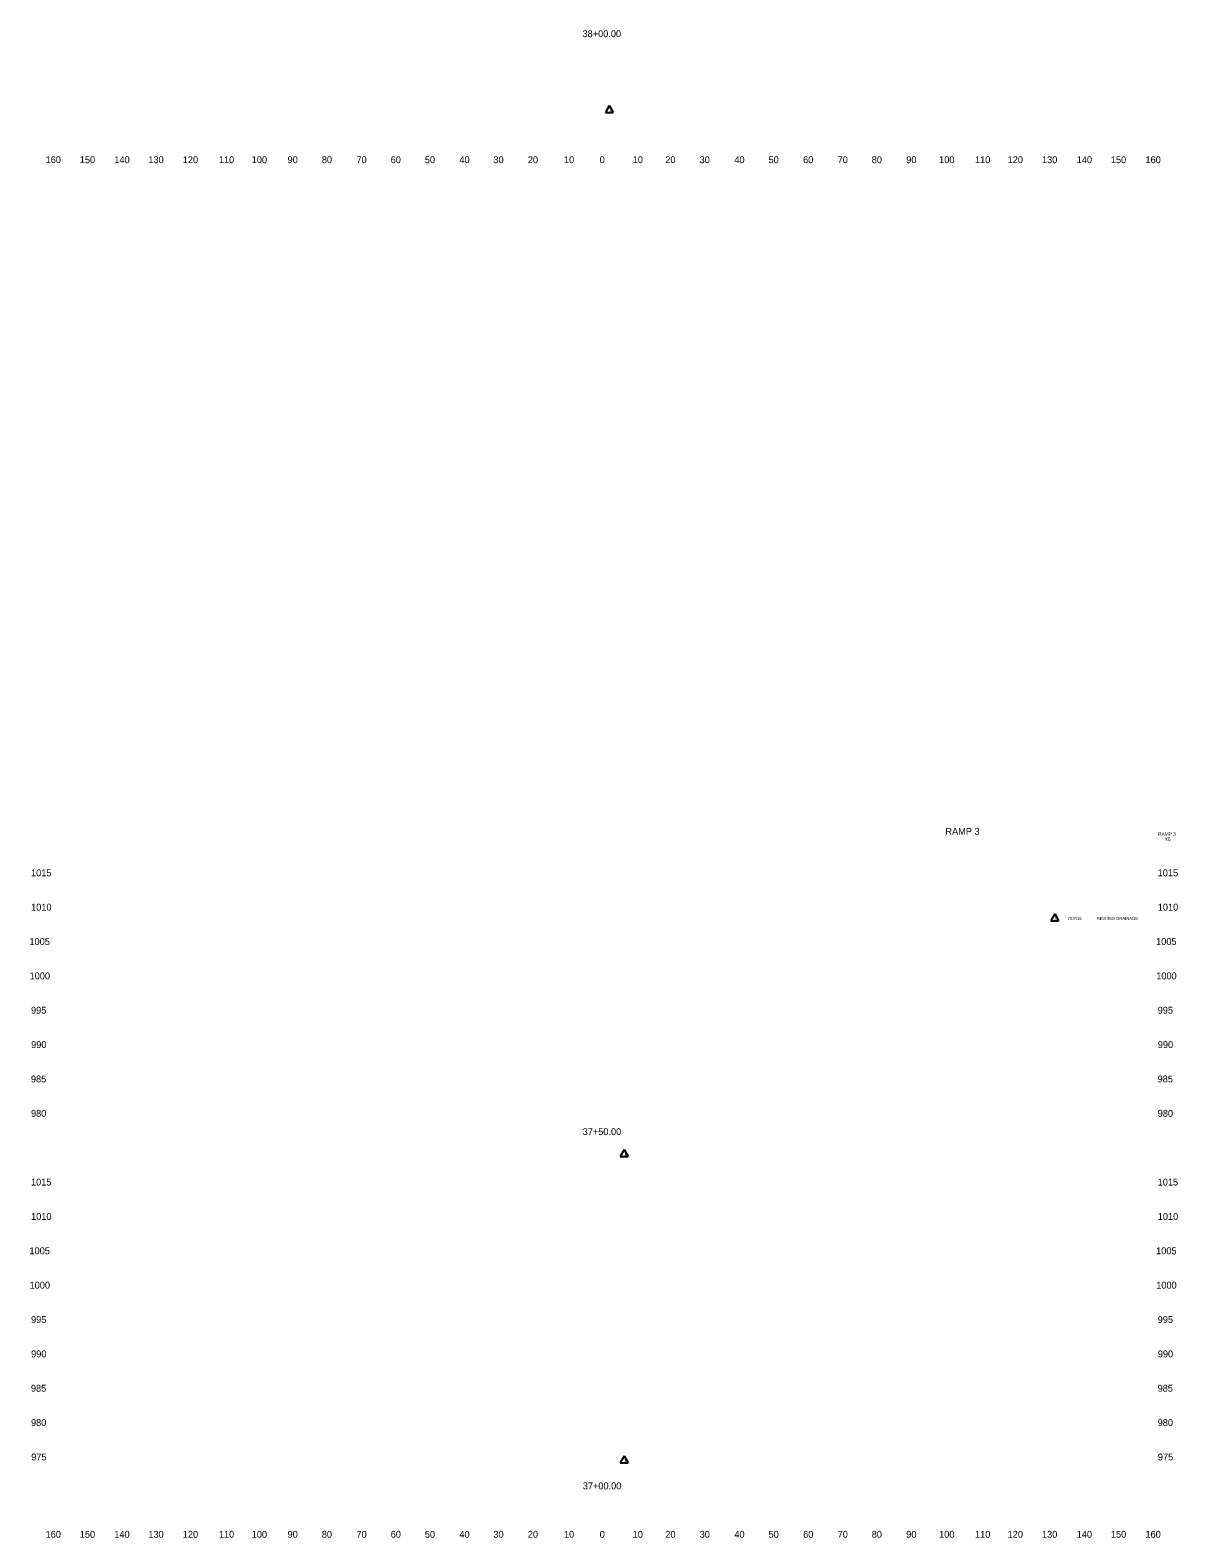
# Model space of a CAD drawing. Extents: x 4994 to 5843, y 4997 to 8804.
# Drawn here: x 4993.6 to 5327.5, y 6997.5 to 7436.2 of the extents above; entities that cross this region are included whole.
import ezdxf

# ---------------------------------------------------------------- set-up
doc = ezdxf.new("R2010")
doc.units = 0
for name, color, linetype in [('RD_SHT_ID', 7, 'Continuous'), ('RD_SHT_TX', 7, 'Continuous'), ('RD_XS_TX_Offset', 7, 'Continuous'), ('RD_XS_TX_Station', 7, 'Continuous')]:
    doc.layers.add(name, color=color, linetype=linetype)

msp = doc.modelspace()

# ---------------------------------------------------------------- linework, layer by layer
at = {"layer": 'RD_SHT_TX'}
for p, q in [((5162.11, 7414.29), (5160.97, 7412.26)), ((5160.97, 7412.26), (5163.25, 7412.26)), ((5162.11, 7414.29), (5163.25, 7412.26)), ((5291.7, 7179.04), (5290.56, 7177.01)), ((5291.7, 7179.04), (5292.84, 7177.01)), ((5290.56, 7177.01), (5292.84, 7177.01)), ((5166.41, 7110.44), (5165.27, 7108.41)), ((5165.27, 7108.41), (5167.55, 7108.41)), ((5166.41, 7110.44), (5167.55, 7108.41)), ((5166.41, 7021.34), (5165.27, 7019.31)), ((5166.41, 7021.34), (5167.55, 7019.31)), ((5165.27, 7019.31), (5167.55, 7019.31))]:
    msp.add_line(p, q, dxfattribs=at)

# ---------------------------------------------------------------- texts
at = {"layer": 'RD_SHT_ID'}
for s, height, p in [('RAMP 3', 2, (5259.89, 7202.06)), ('RAMP 3', 1, (5321.78, 7201.8)), ('X6', 1, (5323.71, 7200.3))]:
    msp.add_text(s, height=height, dxfattribs=at).set_placement(p)
at = {"layer": 'RD_SHT_TX'}
for s, p in [('1', (5162.11, 7412.59)), ('1', (5291.7, 7177.34)), ('7/07/16', (5295.48, 7177.3)), ('REVISED DRAINAGE', (5303.93, 7177.3)), ('1', (5166.41, 7108.74)), ('1', (5166.41, 7019.63))]:
    msp.add_text(s, height=0.88, dxfattribs=at).set_placement(p)
at = {"layer": 'RD_XS_TX_Offset'}
for s, p in [('160', (4998.1, 7397.5)), ('150', (5008.04, 7397.5)), ('140', (5018.1, 7397.5)), ('130', (5027.99, 7397.5)), ('120', (5038.01, 7397.5)), ('110', (5048.51, 7397.5)), ('100', (5058.07, 7397.5)), ('90', (5068.5, 7397.5)), ('80', (5078.46, 7397.5)), ('70', (5088.54, 7397.5)), ('60', (5098.5, 7397.5)), ('50', (5108.43, 7397.5)), ('40', (5118.5, 7397.5)), ('30', (5128.39, 7397.5)), ('20', (5138.4, 7397.5)), ('10', (5148.91, 7397.5)), ('0', (5159.3, 7397.5)), ('0', (5159.3, 7397.5)), ('10', (5168.91, 7397.5)), ('20', (5178.4, 7397.5)), ('30', (5188.39, 7397.5)), ('40', (5198.5, 7397.5)), ('50', (5208.43, 7397.5)), ('60', (5218.5, 7397.5)), ('70', (5228.54, 7397.5)), ('80', (5238.46, 7397.5)), ('90', (5248.5, 7397.5)), ('100', (5258.07, 7397.5)), ('110', (5268.51, 7397.5)), ('120', (5278.01, 7397.5)), ('130', (5287.99, 7397.5)), ('140', (5298.1, 7397.5)), ('150', (5308.04, 7397.5)), ('160', (5318.1, 7397.5)), ('1015', (4993.85, 7190)), ('1015', (5321.65, 7190)), ('1010', (4993.88, 7180)), ('1010', (5321.68, 7180)), ('1005', (4993.4, 7170)), ('1005', (5321.2, 7170)), ('1000', (4993.44, 7160)), ('1000', (5321.24, 7160)), ('995', (4993.86, 7150)), ('995', (5321.66, 7150)), ('990', (4993.89, 7140)), ('990', (5321.69, 7140)), ('985', (4993.83, 7130)), ('985', (5321.63, 7130)), ('980', (4993.86, 7120)), ('980', (5321.66, 7120)), ('1015', (4993.85, 7100)), ('1015', (5321.65, 7100)), ('1010', (4993.88, 7090)), ('1010', (5321.68, 7090)), ('1005', (4993.4, 7080)), ('1005', (5321.2, 7080)), ('1000', (4993.44, 7070)), ('1000', (5321.24, 7070)), ('995', (4993.86, 7060)), ('995', (5321.66, 7060)), ('990', (4993.89, 7050)), ('990', (5321.69, 7050)), ('985', (4993.83, 7040)), ('985', (5321.63, 7040)), ('980', (4993.86, 7030)), ('980', (5321.66, 7030)), ('975', (4993.91, 7020)), ('975', (5321.71, 7020)), ('160', (4998.1, 6997.5)), ('150', (5008.04, 6997.5)), ('140', (5018.1, 6997.5)), ('130', (5027.99, 6997.5)), ('120', (5038.01, 6997.5)), ('110', (5048.51, 6997.5)), ('100', (5058.07, 6997.5)), ('90', (5068.5, 6997.5)), ('80', (5078.46, 6997.5)), ('70', (5088.54, 6997.5)), ('60', (5098.5, 6997.5)), ('50', (5108.43, 6997.5)), ('40', (5118.5, 6997.5)), ('30', (5128.39, 6997.5)), ('20', (5138.4, 6997.5)), ('10', (5148.91, 6997.5)), ('0', (5159.3, 6997.5)), ('0', (5159.3, 6997.5)), ('10', (5168.91, 6997.5)), ('20', (5178.4, 6997.5)), ('30', (5188.39, 6997.5)), ('40', (5198.5, 6997.5)), ('50', (5208.43, 6997.5)), ('60', (5218.5, 6997.5)), ('70', (5228.54, 6997.5)), ('80', (5238.46, 6997.5)), ('90', (5248.5, 6997.5)), ('100', (5258.07, 6997.5)), ('110', (5268.51, 6997.5)), ('120', (5278.01, 6997.5)), ('130', (5287.99, 6997.5)), ('140', (5298.1, 6997.5)), ('150', (5308.04, 6997.5)), ('160', (5318.1, 6997.5))]:
    msp.add_text(s, height=2, dxfattribs=at).set_placement(p)
at = {"layer": 'RD_XS_TX_Station'}
for s, p in [('38+00.00', (5154.31, 7434.17)), ('37+50.00', (5154.35, 7114.67)), ('37+00.00', (5154.39, 7011.6))]:
    msp.add_text(s, height=2, dxfattribs=at).set_placement(p)

doc.saveas('drawing.dxf')
